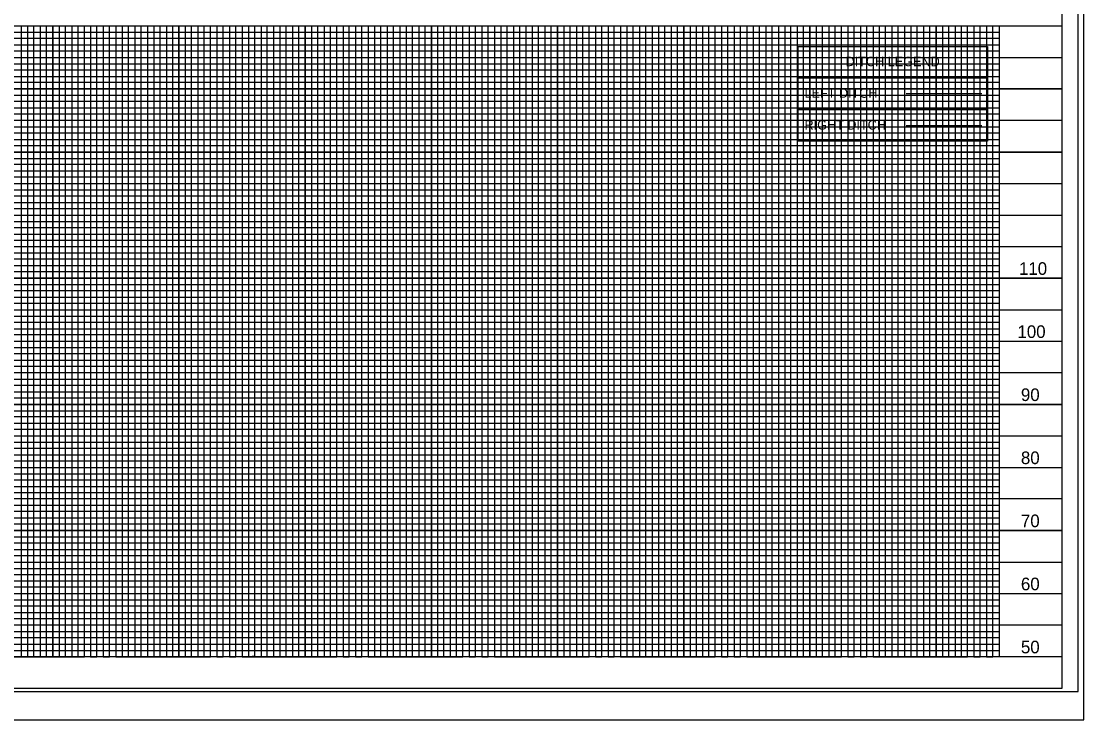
# Model space of a CAD drawing. Extents: x 2367285 to 2374385, y 803279 to 808979.
# Drawn here: x 2373543 to 2374385, y 803279 to 803833 of the extents above; entities that cross this region are included whole.
import ezdxf

# ---------------------------------------------------------------- set-up
doc = ezdxf.new("R2010")
doc.units = 0
for name, color, linetype in [('Old_Level_11', 7, 'Continuous'), ('Old_Level_12', 7, 'Continuous'), ('Old_Level_13', 7, 'Continuous'), ('Old_Level_15', 7, 'Continuous'), ('Old_Level_17', 7, 'Continuous'), ('Old_Level_4', 7, 'Continuous'), ('Old_Level_5', 7, 'Continuous'), ('Old_Level_6', 7, 'Continuous'), ('Old_Level_60', 7, 'Continuous'), ('Old_Level_8', 7, 'Continuous'), ('Old_Level_9', 7, 'Continuous'), ('Text', 7, 'Continuous')]:
    doc.layers.add(name, color=color, linetype=linetype)

msp = doc.modelspace()

# ---------------------------------------------------------------- linework, layer by layer
at = {"layer": 'Old_Level_11'}
for p, q in [((2373567.97, 803828.98), (2373617.97, 803828.98)), ((2373667.97, 803828.98), (2373717.97, 803828.98)), ((2373767.97, 803828.98), (2373817.97, 803828.98)), ((2373867.97, 803828.98), (2373917.97, 803828.98)), ((2373967.97, 803828.98), (2374017.97, 803828.98)), ((2374067.97, 803828.98), (2374117.97, 803828.98)), ((2374167.97, 803828.98), (2374217.97, 803828.98)), ((2374267.97, 803828.98), (2374317.97, 803828.98)), ((2374267.97, 803328.98), (2374267.97, 803328.98))]:
    msp.add_line(p, q, dxfattribs=at)
for points in [[(2373517.97, 803328.98), (2373567.97, 803328.98), (2373567.97, 803828.98), (2373617.97, 803828.98), (2373617.97, 803328.98), (2373667.97, 803328.98), (2373667.97, 803828.98), (2373717.97, 803828.98), (2373717.97, 803328.98), (2373767.97, 803328.98), (2373767.97, 803828.98), (2373817.97, 803828.98), (2373817.97, 803328.98), (2373867.97, 803328.98), (2373867.97, 803828.98), (2373917.97, 803828.98), (2373917.97, 803328.98), (2373967.97, 803328.98), (2373967.97, 803828.98), (2374017.97, 803828.98), (2374017.97, 803328.98), (2374067.97, 803328.98), (2374067.97, 803828.98), (2374117.97, 803828.98), (2374117.97, 803328.98), (2374167.97, 803328.98), (2374167.97, 803828.98), (2374217.97, 803828.98), (2374217.97, 803328.98), (2374267.97, 803328.98), (2374267.97, 803328.98), (2374267.97, 803828.98), (2374317.97, 803828.98), (2374317.97, 803328.98)], [(2374367.97, 803778.98), (2372867.97, 803778.98)], [(2374367.97, 803728.98), (2372867.97, 803728.98), (2372867.97, 803678.98), (2374367.97, 803678.98)], [(2374367.97, 803628.98), (2372867.97, 803628.98), (2372867.97, 803578.98), (2374367.97, 803578.98)], [(2374367.97, 803528.98), (2372867.97, 803528.98), (2372867.97, 803478.98), (2374367.97, 803478.98)], [(2374367.97, 803428.98), (2372867.97, 803428.98), (2372867.97, 803428.98), (2372867.97, 803378.98), (2374367.97, 803378.98)], [(2374367.97, 803328.98), (2372867.97, 803328.98)]]:
    msp.add_lwpolyline(points, dxfattribs=at)
at = {"layer": 'Old_Level_12'}
for points in [[(2373492.97, 803828.98), (2373542.97, 803828.98), (2373542.97, 803328.98), (2373592.97, 803328.98), (2373592.97, 803828.98), (2373642.97, 803828.98), (2373642.97, 803328.98), (2373692.97, 803328.98), (2373692.97, 803828.98), (2373742.97, 803828.98), (2373742.97, 803328.98), (2373792.97, 803328.98), (2373792.97, 803828.98), (2373842.97, 803828.98), (2373842.97, 803328.98), (2373892.97, 803328.98), (2373892.97, 803828.98), (2373942.97, 803828.98), (2373942.97, 803328.98), (2373992.97, 803328.98), (2373992.97, 803828.98), (2374042.97, 803828.98), (2374042.97, 803328.98), (2374092.97, 803328.98), (2374092.97, 803828.98), (2374142.97, 803828.98), (2374142.97, 803328.98), (2374192.97, 803328.98), (2374192.97, 803828.98), (2374242.97, 803828.98), (2374242.97, 803328.98), (2374292.97, 803328.98), (2374292.97, 803828.98)], [(2372867.97, 803803.98), (2374367.97, 803803.98)], [(2374367.97, 803753.98), (2372867.97, 803753.98), (2372867.97, 803703.98), (2374367.97, 803703.98)], [(2374367.97, 803653.98), (2372867.97, 803653.98), (2372867.97, 803603.98), (2374367.97, 803603.98)], [(2374367.97, 803553.98), (2372867.97, 803553.98), (2372867.97, 803503.98), (2374367.97, 803503.98)], [(2374367.97, 803453.98), (2372867.97, 803453.98), (2372867.97, 803403.98), (2374367.97, 803403.98)], [(2374367.97, 803353.98), (2372867.97, 803353.98)]]:
    msp.add_lwpolyline(points, dxfattribs=at)
at = {"layer": 'Old_Level_13'}
for p, q in [((2372867.97, 803828.98), (2374367.86, 803828.98)), ((2373567.97, 803828.98), (2373567.97, 803328.98)), ((2373617.97, 803828.98), (2373617.97, 803328.98)), ((2373667.97, 803828.98), (2373667.97, 803328.98)), ((2373717.97, 803828.98), (2373717.97, 803328.98)), ((2373767.97, 803828.98), (2373767.97, 803328.98)), ((2373817.97, 803828.98), (2373817.97, 803328.98)), ((2373867.97, 803828.98), (2373867.97, 803328.98)), ((2373917.97, 803828.98), (2373917.97, 803328.98)), ((2373967.97, 803828.98), (2373967.97, 803328.98)), ((2374017.97, 803828.98), (2374017.97, 803328.98)), ((2374067.97, 803828.98), (2374067.97, 803328.98)), ((2374117.97, 803828.98), (2374117.97, 803328.98)), ((2374167.97, 803828.98), (2374167.97, 803328.98)), ((2374217.97, 803828.98), (2374217.97, 803328.98)), ((2374267.97, 803828.98), (2374267.97, 803328.98)), ((2374317.97, 803828.98), (2374317.97, 803328.98)), ((2372867.97, 803778.98), (2374367.86, 803778.98)), ((2372867.97, 803728.98), (2374367.86, 803728.98)), ((2372867.97, 803678.98), (2374367.86, 803678.98)), ((2372867.97, 803628.98), (2374367.86, 803628.98)), ((2372867.97, 803578.98), (2374367.86, 803578.98)), ((2372867.97, 803528.98), (2374367.86, 803528.98)), ((2372867.97, 803478.98), (2374367.86, 803478.98)), ((2372867.97, 803428.98), (2374367.86, 803428.98)), ((2372867.97, 803378.98), (2374367.86, 803378.98))]:
    msp.add_line(p, q, dxfattribs=at)
at = {"layer": 'Old_Level_15'}
msp.add_line((2372700.97, 803278.98), (2374384.97, 803278.98), dxfattribs=at)
at = {"layer": 'Old_Level_4'}
msp.add_lwpolyline([(2372713.97, 803301.43), (2374380.47, 803301.43), (2374380.47, 804356.53), (2372713.97, 804356.53)], close=True, dxfattribs=at)
at = {"layer": 'Old_Level_5'}
msp.add_lwpolyline([(2372917.97, 803828.98), (2374317.97, 803828.98), (2374317.97, 803328.98), (2372917.97, 803328.98)], close=True, dxfattribs=at)
at = {"layer": 'Old_Level_6'}
msp.add_lwpolyline([(2372700.97, 803278.98), (2374384.97, 803278.98), (2374384.97, 804378.98), (2372700.97, 804378.98)], close=True, dxfattribs=at)
at = {"layer": 'Old_Level_60'}
for points in [[(2374158.71, 803812.68), (2374308.71, 803812.68), (2374308.71, 803787.68), (2374158.71, 803787.68)], [(2374158.71, 803787.68), (2374308.71, 803787.68), (2374308.71, 803762.68), (2374158.71, 803762.68)], [(2374158.71, 803762.68), (2374308.71, 803762.68), (2374308.71, 803737.68), (2374158.71, 803737.68)]]:
    msp.add_lwpolyline(points, close=True, dxfattribs=at)
at = {"layer": 'Old_Level_8'}
for p, q in [((2372917.97, 803823.98), (2374317.97, 803823.98)), ((2374317.97, 803818.98), (2372917.97, 803818.98)), ((2372917.97, 803813.98), (2374317.97, 803813.98)), ((2374317.97, 803808.98), (2372917.97, 803808.98)), ((2372917.97, 803798.98), (2374317.97, 803798.98)), ((2374317.97, 803793.98), (2372917.97, 803793.98)), ((2372917.97, 803788.98), (2374317.97, 803788.98)), ((2374317.97, 803783.98), (2372917.97, 803783.98)), ((2372917.97, 803773.98), (2374317.97, 803773.98)), ((2374317.97, 803768.98), (2372917.97, 803768.98)), ((2372917.97, 803763.98), (2374317.97, 803763.98)), ((2374317.97, 803758.98), (2372917.97, 803758.98)), ((2372917.97, 803748.98), (2374317.97, 803748.98)), ((2374317.97, 803743.98), (2372917.97, 803743.98)), ((2372917.97, 803738.98), (2374317.97, 803738.98)), ((2374317.97, 803733.98), (2372917.97, 803733.98)), ((2372917.97, 803723.98), (2374317.97, 803723.98)), ((2374317.97, 803718.98), (2372917.97, 803718.98)), ((2372917.97, 803713.98), (2374317.97, 803713.98)), ((2374317.97, 803708.98), (2372917.97, 803708.98)), ((2372917.97, 803698.98), (2374317.97, 803698.98)), ((2374317.97, 803693.98), (2372917.97, 803693.98)), ((2372917.97, 803688.98), (2374317.97, 803688.98)), ((2374317.97, 803683.98), (2372917.97, 803683.98)), ((2372917.97, 803673.98), (2374317.97, 803673.98)), ((2374317.97, 803668.98), (2372917.97, 803668.98)), ((2372917.97, 803663.98), (2374317.97, 803663.98)), ((2374317.97, 803658.98), (2372917.97, 803658.98)), ((2372917.97, 803648.98), (2374317.97, 803648.98)), ((2374317.97, 803643.98), (2372917.97, 803643.98)), ((2372917.97, 803638.98), (2374317.97, 803638.98)), ((2374317.97, 803633.98), (2372917.97, 803634.13)), ((2372917.97, 803623.98), (2374317.97, 803623.98)), ((2374317.97, 803618.98), (2372917.97, 803618.98)), ((2372917.97, 803613.98), (2374317.97, 803613.98)), ((2374317.97, 803608.98), (2372917.97, 803608.98)), ((2372917.97, 803598.98), (2374317.97, 803598.98)), ((2374317.97, 803593.98), (2372917.97, 803593.98)), ((2372917.97, 803588.98), (2374317.97, 803588.98)), ((2374317.97, 803583.98), (2372917.97, 803583.98)), ((2372917.97, 803573.98), (2374317.97, 803573.98)), ((2374317.97, 803568.98), (2372917.97, 803568.98)), ((2372917.97, 803563.98), (2374317.97, 803563.98)), ((2374317.97, 803558.98), (2372917.97, 803558.98)), ((2372917.97, 803548.98), (2374317.97, 803548.98)), ((2374317.97, 803543.98), (2372917.97, 803543.98)), ((2372917.97, 803538.98), (2374317.97, 803538.98)), ((2374317.97, 803533.98), (2372917.97, 803533.98)), ((2372917.97, 803523.98), (2374317.97, 803523.98)), ((2374317.97, 803518.98), (2372917.97, 803518.98)), ((2372917.97, 803513.98), (2374317.97, 803513.98)), ((2374317.97, 803508.98), (2372917.97, 803508.98)), ((2372917.97, 803498.98), (2374317.97, 803498.98)), ((2374317.97, 803493.98), (2372917.97, 803493.98)), ((2372917.97, 803488.98), (2374317.97, 803488.98)), ((2374317.97, 803483.98), (2372917.97, 803483.98)), ((2372917.97, 803473.98), (2374317.97, 803473.98)), ((2374317.97, 803468.98), (2372917.97, 803468.98)), ((2372917.97, 803463.98), (2374317.97, 803463.98)), ((2374317.97, 803458.98), (2372917.97, 803458.98)), ((2372917.97, 803448.98), (2374317.97, 803448.98)), ((2374317.97, 803443.98), (2372917.97, 803443.98)), ((2372917.97, 803438.98), (2374317.97, 803438.98)), ((2374317.97, 803433.98), (2372917.97, 803433.98)), ((2372917.97, 803423.98), (2374317.97, 803423.98)), ((2374317.97, 803418.98), (2372917.97, 803418.98)), ((2372917.97, 803413.98), (2374317.97, 803413.98)), ((2374317.97, 803408.98), (2372917.97, 803408.98)), ((2372917.97, 803398.98), (2374317.97, 803398.98)), ((2374317.97, 803393.98), (2372917.97, 803393.98)), ((2372917.97, 803388.98), (2374317.97, 803388.98)), ((2374317.97, 803383.98), (2372917.97, 803383.98)), ((2372917.97, 803373.98), (2374317.97, 803373.98)), ((2374317.97, 803368.98), (2372917.97, 803368.98)), ((2372917.97, 803363.98), (2374317.97, 803363.98)), ((2374317.97, 803358.98), (2372917.97, 803358.98)), ((2372917.97, 803348.98), (2374317.97, 803348.98)), ((2374317.97, 803343.98), (2372917.97, 803343.98)), ((2372917.97, 803338.98), (2374317.97, 803338.98)), ((2372917.97, 803333.98), (2374317.97, 803333.98)), ((2374317.97, 803333.98), (2374317.97, 803333.98))]:
    msp.add_line(p, q, dxfattribs=at)
for points in [[(2373537.97, 803828.98), (2373547.97, 803828.98), (2373547.97, 803328.98), (2373552.97, 803328.98), (2373552.97, 803828.98), (2373557.97, 803828.98), (2373557.97, 803328.98), (2373562.97, 803328.98), (2373562.97, 803828.98), (2373572.97, 803828.98), (2373572.97, 803328.98), (2373572.97, 803328.98), (2373577.97, 803328.98), (2373577.97, 803828.98), (2373582.97, 803828.98), (2373582.97, 803328.98), (2373587.97, 803328.98), (2373587.97, 803828.98), (2373597.97, 803828.98), (2373597.97, 803328.98), (2373602.97, 803328.98), (2373602.97, 803828.98), (2373607.97, 803828.98), (2373607.97, 803328.98), (2373612.97, 803328.98), (2373612.97, 803828.98), (2373622.97, 803828.98), (2373622.97, 803328.98), (2373627.97, 803328.98), (2373627.97, 803828.98), (2373632.97, 803828.98), (2373632.97, 803328.98), (2373637.97, 803328.98), (2373637.97, 803828.98), (2373647.97, 803828.98), (2373647.97, 803328.98), (2373652.97, 803328.98), (2373652.97, 803828.98), (2373657.97, 803828.98), (2373657.97, 803328.98), (2373662.97, 803328.98), (2373662.97, 803828.98), (2373672.97, 803828.98), (2373672.97, 803328.98), (2373677.97, 803328.98), (2373677.97, 803828.98), (2373682.97, 803828.98), (2373682.97, 803328.98), (2373687.97, 803328.98), (2373687.97, 803828.98), (2373697.97, 803828.98), (2373697.97, 803328.98), (2373702.97, 803328.98), (2373702.97, 803828.98), (2373707.97, 803828.98), (2373707.97, 803328.98), (2373712.97, 803328.98), (2373712.97, 803828.98), (2373722.97, 803828.98), (2373722.97, 803328.98), (2373727.67, 803329.53), (2373727.97, 803328.98), (2373727.97, 803828.98), (2373732.97, 803828.98), (2373732.97, 803328.98), (2373737.97, 803328.98), (2373737.97, 803828.98), (2373747.97, 803828.98), (2373747.97, 803328.98), (2373752.97, 803328.98)], [(2373752.97, 803328.98), (2373752.97, 803828.98), (2373757.97, 803828.98), (2373757.97, 803328.98), (2373762.97, 803328.98), (2373762.97, 803828.98), (2373772.97, 803828.98), (2373772.97, 803328.98), (2373777.97, 803328.98), (2373777.97, 803828.98), (2373782.97, 803828.98), (2373782.97, 803328.98), (2373787.97, 803328.98), (2373787.97, 803828.98), (2373797.97, 803828.98), (2373797.97, 803328.98), (2373802.97, 803328.98), (2373802.97, 803828.98), (2373807.97, 803828.98), (2373807.97, 803328.98), (2373812.97, 803328.98), (2373812.97, 803828.98), (2373822.97, 803828.98), (2373822.97, 803328.98), (2373827.97, 803328.98), (2373827.97, 803828.98), (2373832.97, 803828.98), (2373832.97, 803328.98), (2373837.97, 803328.98), (2373837.97, 803828.98), (2373847.97, 803828.98), (2373847.97, 803328.98), (2373852.97, 803328.98), (2373852.97, 803828.98), (2373857.97, 803828.98), (2373857.97, 803328.98), (2373862.97, 803328.98), (2373862.97, 803828.98), (2373872.97, 803828.98), (2373872.97, 803328.98), (2373877.97, 803328.98), (2373877.97, 803828.98), (2373882.97, 803828.98), (2373882.97, 803328.98), (2373887.97, 803328.98), (2373887.97, 803828.98), (2373897.97, 803828.98), (2373897.97, 803328.98), (2373902.97, 803328.98), (2373902.97, 803828.98), (2373907.97, 803828.98), (2373907.97, 803328.98), (2373912.97, 803328.98), (2373912.97, 803828.98), (2373922.97, 803828.98), (2373922.97, 803328.98), (2373927.97, 803328.98), (2373927.97, 803828.98), (2373932.97, 803828.98), (2373932.97, 803328.98), (2373937.97, 803328.98), (2373937.97, 803828.98), (2373947.97, 803828.98), (2373947.97, 803328.98), (2373952.97, 803328.98), (2373952.97, 803828.98), (2373957.97, 803828.98), (2373957.97, 803328.98), (2373962.97, 803328.98), (2373962.97, 803828.98), (2373972.97, 803828.98), (2373972.97, 803328.98), (2373977.97, 803328.98), (2373977.97, 803828.98), (2373982.97, 803828.98), (2373982.97, 803328.98), (2373987.97, 803328.98), (2373987.97, 803828.98), (2373997.97, 803828.98), (2373997.97, 803328.98), (2374002.97, 803328.98), (2374002.97, 803828.98), (2374007.97, 803828.98), (2374007.97, 803328.98), (2374012.97, 803328.98), (2374012.97, 803828.98), (2374022.97, 803828.98), (2374022.97, 803328.98), (2374027.97, 803328.98), (2374027.97, 803828.98), (2374032.97, 803828.98), (2374032.97, 803328.98), (2374037.97, 803328.98), (2374037.97, 803828.98), (2374047.97, 803828.98), (2374047.97, 803328.98), (2374052.97, 803328.98), (2374052.97, 803828.98), (2374057.97, 803828.98), (2374057.97, 803328.98)], [(2374057.97, 803328.98), (2374062.97, 803328.98), (2374062.97, 803828.98), (2374072.97, 803828.98), (2374072.97, 803328.98), (2374077.97, 803328.98), (2374077.97, 803828.98), (2374082.97, 803828.98), (2374082.97, 803328.98), (2374087.97, 803328.98), (2374087.97, 803828.98), (2374097.97, 803828.98), (2374097.97, 803328.98), (2374102.97, 803328.98), (2374102.97, 803828.98), (2374107.97, 803828.98), (2374107.97, 803328.98), (2374112.97, 803328.98), (2374112.97, 803828.98), (2374122.97, 803828.98), (2374122.97, 803328.98), (2374127.97, 803328.98), (2374127.97, 803828.98), (2374132.97, 803828.98), (2374132.97, 803328.98), (2374137.97, 803328.98), (2374137.97, 803828.98), (2374147.97, 803828.98), (2374147.97, 803328.98), (2374152.97, 803328.98), (2374152.97, 803828.98), (2374157.97, 803828.98), (2374157.97, 803328.98), (2374162.97, 803328.98), (2374162.97, 803828.98), (2374172.97, 803828.98), (2374172.97, 803328.98), (2374177.97, 803328.98), (2374177.97, 803828.98), (2374182.97, 803828.98), (2374182.97, 803328.98), (2374187.97, 803328.98), (2374187.97, 803828.98), (2374197.97, 803828.98), (2374197.97, 803328.98), (2374202.97, 803328.98), (2374202.97, 803828.98), (2374207.97, 803828.98), (2374207.97, 803328.98), (2374212.97, 803328.98), (2374212.97, 803828.98), (2374222.97, 803828.98), (2374222.97, 803328.98), (2374227.97, 803328.98), (2374227.97, 803828.98), (2374232.97, 803828.98), (2374232.97, 803328.98), (2374237.97, 803328.98), (2374237.97, 803828.98), (2374247.97, 803828.98), (2374247.97, 803328.98), (2374252.97, 803328.98), (2374252.97, 803828.98), (2374257.97, 803828.98), (2374257.97, 803328.98), (2374262.97, 803328.98), (2374262.97, 803828.98), (2374272.97, 803828.98), (2374272.97, 803328.98), (2374277.97, 803328.98), (2374277.97, 803828.98), (2374282.97, 803828.98), (2374282.97, 803328.98), (2374287.97, 803328.98), (2374287.97, 803828.98), (2374297.97, 803828.98), (2374297.97, 803328.98), (2374302.97, 803328.98), (2374302.97, 803828.98), (2374307.97, 803828.98), (2374307.97, 803328.98), (2374312.97, 803328.98), (2374312.97, 803828.98), (2374317.97, 803828.98)]]:
    msp.add_lwpolyline(points, dxfattribs=at)
at = {"layer": 'Old_Level_9'}
for p, q in [((2372867.97, 803828.98), (2374367.97, 803828.98)), ((2374367.97, 803328.98), (2372867.97, 803328.98)), ((2372867.97, 803303.98), (2374367.97, 803303.98))]:
    msp.add_line(p, q, dxfattribs=at)
msp.add_lwpolyline([(2374367.97, 804353.98), (2372867.97, 804353.98), (2372867.97, 803303.98), (2374367.97, 803303.98)], close=True, dxfattribs=at)
at = {"layer": 'Text'}
for p, q in [((2374244.26, 803775.38), (2374304.26, 803775.38)), ((2374244.26, 803750.03), (2374304.26, 803750.03)), ((2374158.71, 803747.68), (2374158.71, 803747.68))]:
    msp.add_line(p, q, dxfattribs=at)

# ---------------------------------------------------------------- texts
at = {"layer": 'Old_Level_17'}
for s, p in [('110', (2374333.62, 803631.63)), ('110', (2374333.62, 803631.63)), ('100', (2374332.43, 803581.63)), ('100', (2374332.43, 803581.63)), ('90', (2374335.18, 803531.63)), ('90', (2374335.18, 803531.63)), ('80', (2374335.18, 803481.63)), ('80', (2374335.18, 803481.63)), ('70', (2374335.18, 803431.63)), ('70', (2374335.18, 803431.63)), ('60', (2374335.18, 803381.63)), ('60', (2374335.18, 803381.63)), ('50', (2374335.18, 803331.63)), ('50', (2374335.18, 803331.63))]:
    msp.add_text(s, height=10, dxfattribs=at).set_placement(p)
at = {"layer": 'Text'}
for s, height, p in [('DITCH LEGEND', 7.5, (2374196.21, 803797.03)), ('LEFT DITCH', 7.485, (2374163.71, 803771.98)), ('RIGHT DITCH', 7.485, (2374163.71, 803746.78))]:
    msp.add_text(s, height=height, dxfattribs=at).set_placement(p)

doc.saveas('drawing.dxf')
